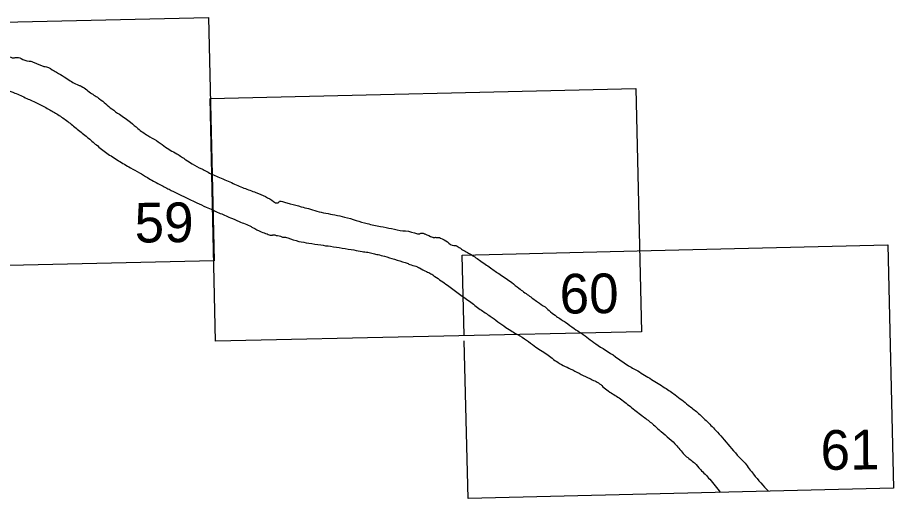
# Model space of a CAD drawing. Extents: x 3734862 to 3772949, y 391520 to 417239.
# Drawn here: x 3759905 to 3762489, y 394372 to 395791 of the extents above; entities that cross this region are included whole.
import ezdxf

# ---------------------------------------------------------------- set-up
doc = ezdxf.new("R2010")
doc.units = 0
doc.layers.add('V-ANNO-NPLT', color=7, linetype='Continuous')

msp = doc.modelspace()

# ---------------------------------------------------------------- linework, layer by layer
at = {"layer": 'V-ANNO-NPLT'}
for points in [[(3759229.9, 395044.4), (3759213.9, 395762.4), (3760468.2, 395790.9), (3760484.8, 395072.9)], [(3760489.4, 394836.6), (3760473.7, 395551.5), (3761728.2, 395581.1), (3761745.4, 394863.2)], [(3761732.2, 395102.4), (3762471.7, 395120.3), (3762488.5, 394402.3)], [(3761222.4, 394852.8), (3761216.8, 395090), (3761732.2, 395102.4)], [(3760484.8, 395072.9), (3759229.9, 395044.4)], [(3761745.4, 394863.2), (3760489.4, 394836.6)], [(3761233.8, 394372.1), (3761222.8, 394836.7)], [(3762488.5, 394402.3), (3761233.8, 394372.1)]]:
    msp.add_lwpolyline(points, dxfattribs=at)
for points in [[(3759856.7, 395678.1), (3759863.7, 395676.3), (3759869.7, 395675.9), (3759872.4, 395676.4), (3759889.1, 395672.4), (3759893.7, 395672), (3759898.3, 395672.5), (3759902.5, 395673), (3759907.6, 395673.1), (3759915.4, 395670.4), (3759939.1, 395661.9), (3759944.6, 395661.9), (3759953.9, 395658.3), (3759982.6, 395646.6)], [(3759982.6, 395646.6), (3759990.5, 395645.3), (3760013.2, 395633.1), (3760026.2, 395625.8), (3760048, 395612.6), (3760080.6, 395593.1), (3760088.9, 395590), (3760120.1, 395568.6)], [(3759753.9, 395623.4), (3759784.5, 395611.7), (3759797, 395607.2), (3759818.3, 395598.7), (3759852.6, 395584.2), (3759896.7, 395568.1), (3759932.4, 395552.3)], [(3760120.1, 395568.6), (3760147, 395550.9), (3760183.3, 395521.2), (3760205.6, 395505.3), (3760238.2, 395482), (3760260.1, 395463.3)], [(3759932.4, 395552.3), (3759964.8, 395537.4), (3759996.4, 395520.6), (3760024.3, 395504.7)], [(3760024.3, 395504.7), (3760053.1, 395484.3), (3760081, 395461.9), (3760111.3, 395437.3), (3760137.8, 395414.9)], [(3760260.1, 395463.3), (3760289.4, 395442.4), (3760314.5, 395427.9), (3760336.8, 395411.9), (3760375.3, 395388.8)], [(3760137.8, 395414.9), (3760168.1, 395391.2), (3760202.9, 395368.5), (3760238.2, 395347.6), (3760264.7, 395333.1)], [(3760375.3, 395388.8), (3760401.8, 395371), (3760420.4, 395358.8), (3760448.3, 395344.3), (3760478.9, 395328)], [(3760264.7, 395333.1), (3760288.4, 395318.5), (3760323.2, 395299), (3760352.5, 395284.1), (3760401.2, 395260.1), (3760434.1, 395244.3), (3760461.5, 395231.7), (3760481.3, 395223.1)], [(3760478.7, 395328.1), (3760495.9, 395321.1), (3760536.1, 395303.7), (3760573, 395287.8), (3760608.2, 395274.7), (3760636.5, 395262.5), (3760660.4, 395247.7), (3760665.3, 395244.5), (3760670.1, 395244), (3760676.1, 395245.7), (3760677.6, 395248.9), (3760683, 395249), (3760695.5, 395244.8), (3760709.6, 395241.7), (3760742.1, 395232.8), (3760763.2, 395227.1)], [(3760481.3, 395223.1), (3760498.7, 395215.1), (3760532.9, 395200.3), (3760558.4, 395189.3), (3760594.2, 395174), (3760598.5, 395171.8)], [(3760763.2, 395227.1), (3760787.6, 395219.8), (3760841.2, 395208.5), (3760869.9, 395202.3), (3760903.5, 395192.4)], [(3760903.5, 395192.4), (3760936.5, 395183), (3760975.5, 395174.7), (3761008.5, 395168.1), (3761041.5, 395161.9), (3761049.6, 395161.5), (3761084.8, 395153.2), (3761089.7, 395152.7), (3761092.9, 395153.8), (3761095.6, 395154.9), (3761098.9, 395155), (3761103.2, 395153.4), (3761106.5, 395152.3), (3761129.2, 395142.8), (3761131.4, 395142.3), (3761136.8, 395142.4), (3761139.5, 395142.4), (3761143.8, 395141.9), (3761147.1, 395142), (3761152.5, 395140.4), (3761173.1, 395128.7)], [(3760598.5, 395171.8), (3760624.1, 395158.6), (3760640.9, 395152.3), (3760653.3, 395148.6), (3760656.6, 395149.2), (3760659.8, 395149.8), (3760667.9, 395148.2), (3760684.7, 395144.1), (3760688.5, 395142.5), (3760691.2, 395143.1), (3760695, 395142.6), (3760702.6, 395140.5), (3760734.5, 395130.6), (3760764.3, 395125.5), (3760799.5, 395119.9), (3760828.1, 395115.9), (3760897.4, 395105.2)], [(3761173.1, 395128.7), (3761191.6, 395118.6), (3761195.4, 395118.7), (3761198.1, 395118.2), (3761211.1, 395110.2), (3761238.9, 395093.7), (3761267.7, 395075.1), (3761300.3, 395052.2), (3761328.1, 395033)], [(3760897.4, 395105.2), (3760921.7, 395100.6), (3760929.8, 395099.6), (3760938, 395098.6), (3760954.2, 395094.5), (3760968.3, 395091.4), (3760987.2, 395086.7), (3761016.5, 395077.8), (3761047.9, 395067.9), (3761054.4, 395065.8), (3761059.3, 395063.7), (3761065.8, 395061.1), (3761084.8, 395055.3), (3761090.2, 395052.1), (3761111.4, 395041.5), (3761123.9, 395035.2), (3761135.9, 395027.2)], [(3761135.9, 395027.2), (3761172.9, 395001.1), (3761204.4, 394977.6), (3761237.6, 394954.2)], [(3761328.1, 395033), (3761362.9, 395009.1), (3761383.6, 394992), (3761411.9, 394971.7), (3761438.6, 394952), (3761460.9, 394937.1)], [(3761237.6, 394954.2), (3761269.8, 394929.7), (3761298.6, 394910), (3761322, 394893.5), (3761344.9, 394876.9)], [(3761460.9, 394937.1), (3761494.7, 394909.3), (3761521.3, 394891.8), (3761546.4, 394873.7), (3761568.4, 394859.4)], [(3761344.9, 394876.9), (3761364.4, 394864.7), (3761379.5, 394855.4)], [(3761568.4, 394859.4), (3761610.2, 394828.5), (3761668.6, 394790.4), (3761702.8, 394766.1), (3761734.3, 394748.4)], [(3761379.5, 394855.4), (3761406.4, 394839), (3761429.2, 394821.9), (3761466.1, 394797.6), (3761498.3, 394773.9), (3761542.5, 394751.1), (3761592.7, 394725.6), (3761621.5, 394710.6), (3761634.9, 394698.7)], [(3761734.3, 394748.4), (3761774.5, 394723.5), (3761814, 394698.6), (3761844.9, 394677.6), (3761883.2, 394647.4), (3761910.7, 394625.6), (3761935.6, 394602.6)], [(3761634.9, 394698.7), (3761651.7, 394686.2), (3761683.2, 394665.9), (3761716.8, 394639.6), (3761751, 394613.3), (3761777.9, 394592.2), (3761803.4, 394569.2)], [(3761935.6, 394602.6), (3761964.5, 394572.9), (3761984.1, 394551.1), (3762027.9, 394500.2), (3762050.8, 394476.5)], [(3761803.4, 394569.2), (3761849.1, 394527.7), (3761875.4, 394497.9), (3761901.6, 394476.9), (3761919.1, 394457.7)], [(3762050.8, 394476.5), (3762075.8, 394443.4), (3762119.7, 394393.4)], [(3761919.1, 394457.7), (3761946.7, 394428.7), (3761977.7, 394389.7)]]:
    msp.add_spline(points, degree=3, dxfattribs=at)

# ---------------------------------------------------------------- texts
for s, p in [('59', (3760250.9, 395126.9)), ('60', (3761504.5, 394917.3)), ('61', (3762273.9, 394456.3))]:
    msp.add_text(s, height=117, rotation=0.6052, dxfattribs=at).set_placement(p)

doc.saveas('drawing.dxf')
